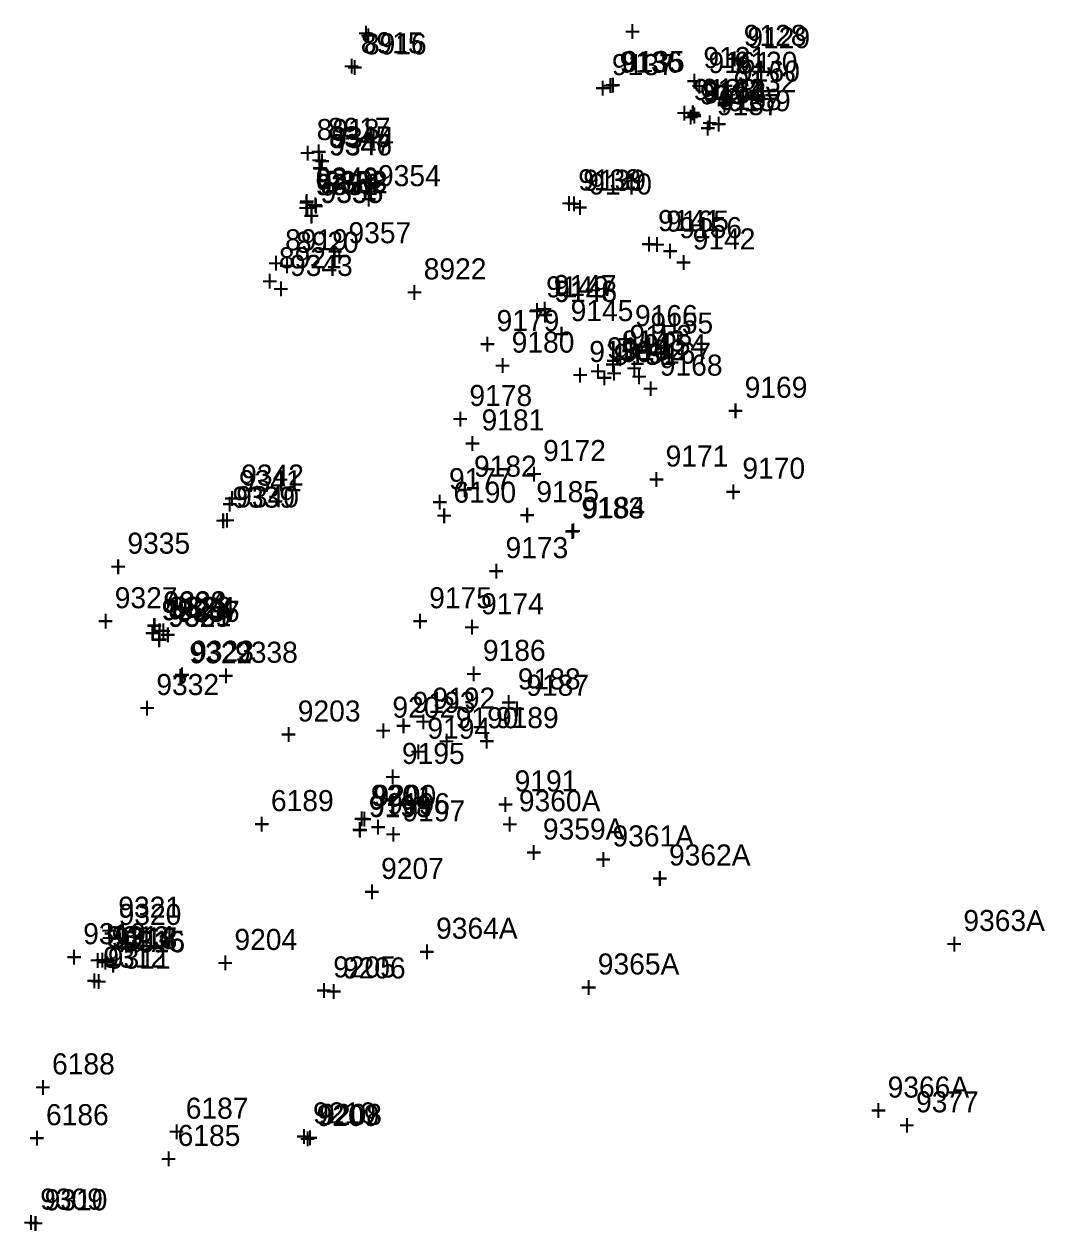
# Model space of a CAD drawing. Extents: x 1136220 to 1137808, y 528804 to 531215.
# Drawn here: x 1136326 to 1136447, y 529376.3 to 529519.5 of the extents above; entities that cross this region are included whole.
import ezdxf

# ---------------------------------------------------------------- set-up
doc = ezdxf.new("R2010")
doc.units = 0
for name, color, linetype in [('S_Buildings', 7, 'Continuous'), ('S_Buildings_SillElevation', 7, 'Continuous'), ('S_Curb_Type_3', 7, 'Continuous'), ('S_Drainage_CB', 7, 'Continuous'), ('S_Drainage_Culvert_Top', 7, 'Continuous'), ('S_Drainage_Invert', 7, 'Continuous'), ('S_Drainage_Sump', 7, 'Continuous'), ('S_Fencing_Picket', 7, 'Continuous'), ('S_Ground_Elevation', 7, 'Continuous'), ('S_Ground_LevelString', 7, 'Continuous'), ('S_Guardrail_Beam', 7, 'Continuous'), ('S_Property_Walkways', 7, 'Continuous'), ('S_Roadway_Centerline', 7, 'Continuous'), ('S_Roadway_Drive_Paved', 7, 'Continuous'), ('S_Roadway_Edge_Pavement', 7, 'Continuous'), ('S_Trees_Conifer_Pay', 7, 'Continuous'), ('S_Trees_Decid_Pay', 7, 'Continuous'), ('S_Trees_TreeLine', 7, 'Continuous'), ('S_Utilities_UG_Gas_Line', 7, 'Continuous'), ('S_Utilities_UG_Sanitary_MH', 7, 'Continuous')]:
    doc.layers.add(name, color=color, linetype=linetype)

msp = doc.modelspace()

# ---------------------------------------------------------------- texts
at = {"layer": 'S_Buildings'}
for s, p in [('9129', (1136411.76, 529516.64)), ('+', (1136409.7, 529513.89)), ('9142', (1136405.28, 529492.76)), ('+', (1136403.22, 529490.01))]:
    msp.add_text(s, height=2.5, dxfattribs=at).set_placement(p)
at = {"layer": 'S_Buildings_SillElevation'}
for s, p in [('9132', (1136410.13, 529511.42)), ('+', (1136408.07, 529508.67))]:
    msp.add_text(s, height=2.5, dxfattribs=at).set_placement(p)
at = {"layer": 'S_Curb_Type_3'}
for s, p in [('+', (1136365.56, 529517.2)), ('8915', (1136365.93, 529516.03)), ('+', (1136363.86, 529513.28)), ('9136', (1136396.62, 529513.74)), ('+', (1136394.56, 529510.99)), ('8918', (1136360.7, 529505.74)), ('+', (1136358.64, 529502.99)), ('9139', (1136392.3, 529499.72)), ('+', (1136390.24, 529496.97)), ('8919', (1136356.96, 529492.66)), ('8921', (1136356.22, 529490.53)), ('+', (1136354.9, 529489.91)), ('+', (1136354.16, 529487.78)), ('9147', (1136388.81, 529487.23)), ('9148', (1136388.87, 529486.55)), ('+', (1136386.75, 529484.48)), ('+', (1136386.81, 529483.8)), ('9341', (1136351.48, 529464.08)), ('9339', (1136350.7, 529462.13)), ('+', (1136349.42, 529461.33)), ('+', (1136348.64, 529459.38)), ('9322', (1136345.61, 529443.67)), ('+', (1136343.55, 529440.92)), ('9321', (1136337.18, 529413.49)), ('+', (1136335.12, 529410.74)), ('9313', (1136335.81, 529409.97)), ('+', (1136333.75, 529407.22)), ('9312', (1136335.41, 529407.55)), ('+', (1136333.35, 529404.8)), ('9209', (1136360.7, 529388.78)), ('+', (1136358.64, 529386.03)), ('9309', (1136327.92, 529378.86)), ('+', (1136325.86, 529376.11))]:
    msp.add_text(s, height=2.5, dxfattribs=at).set_placement(p)
at = {"layer": 'S_Drainage_CB'}
for s, p in [('9344', (1136362.43, 529504.78)), ('+', (1136360.37, 529502.03)), ('9350', (1136360.69, 529499.23)), ('+', (1136358.63, 529496.48)), ('9198', (1136366.92, 529425.41)), ('+', (1136364.86, 529422.66)), ('9315', (1136337.63, 529409.44)), ('+', (1136335.57, 529406.69))]:
    msp.add_text(s, height=2.5, dxfattribs=at).set_placement(p)
at = {"layer": 'S_Drainage_Culvert_Top'}
for s, p in [('9347', (1136362.15, 529503.95)), ('+', (1136360.09, 529501.2)), ('9348', (1136360.58, 529499.85)), ('9354', (1136367.97, 529500.27)), ('9356', (1136361.18, 529498.32)), ('9353', (1136361.62, 529499.58)), ('+', (1136365.9, 529497.52)), ('+', (1136358.52, 529497.1)), ('+', (1136359.56, 529496.83)), ('+', (1136359.12, 529495.57)), ('9357', (1136364.47, 529493.5)), ('+', (1136362.41, 529490.75)), ('9335', (1136338.26, 529456.67)), ('+', (1136336.19, 529453.92)), ('9327', (1136336.76, 529450.2)), ('9334', (1136342.51, 529449.66)), ('9326', (1136342.31, 529448.77)), ('9337', (1136344.15, 529448.58)), ('+', (1136334.7, 529447.45)), ('9331', (1136343.14, 529448.05)), ('+', (1136340.25, 529446.02)), ('+', (1136340.45, 529446.91)), ('+', (1136342.09, 529445.83)), ('+', (1136341.07, 529445.3)), ('9338', (1136351.03, 529443.73)), ('9332', (1136341.69, 529439.9)), ('+', (1136348.97, 529440.98)), ('+', (1136339.62, 529437.15)), ('9202', (1136369.68, 529437.21)), ('+', (1136367.62, 529434.46)), ('9201', (1136367.12, 529426.75)), ('+', (1136365.06, 529424)), ('9319', (1136333.02, 529410.34)), ('9318', (1136336.75, 529409.76)), ('+', (1136330.96, 529407.59)), ('+', (1136334.68, 529407.01))]:
    msp.add_text(s, height=2.5, dxfattribs=at).set_placement(p)
at = {"layer": 'S_Drainage_Invert'}
for s, p in [('9346', (1136362.2, 529503.91)), ('+', (1136360.14, 529501.16)), ('9349', (1136360.61, 529499.99)), ('9355', (1136361.15, 529498.27)), ('9352', (1136361.7, 529499.43)), ('+', (1136358.55, 529497.24)), ('+', (1136359.64, 529496.68)), ('+', (1136359.09, 529495.52)), ('9333', (1136342.56, 529449.71)), ('9325', (1136342.37, 529448.81)), ('9336', (1136344.13, 529448.58)), ('9329', (1136343.1, 529447.99)), ('+', (1136340.31, 529446.06)), ('+', (1136340.5, 529446.96)), ('+', (1136342.07, 529445.83)), ('+', (1136341.03, 529445.24)), ('9200', (1136367.43, 529426.73)), ('+', (1136365.37, 529423.98)), ('9317', (1136336.72, 529409.84)), ('+', (1136334.66, 529407.09))]:
    msp.add_text(s, height=2.5, dxfattribs=at).set_placement(p)
at = {"layer": 'S_Drainage_Sump'}
for s, p in [('9345', (1136362.09, 529504.88)), ('+', (1136360.03, 529502.13)), ('9351', (1136360.55, 529499.22)), ('+', (1136358.49, 529496.47)), ('9328', (1136343.15, 529449.07)), ('+', (1136341.09, 529446.32)), ('9199', (1136366.87, 529425.48)), ('+', (1136364.81, 529422.73)), ('9316', (1136337.67, 529409.38)), ('+', (1136335.61, 529406.63))]:
    msp.add_text(s, height=2.5, dxfattribs=at).set_placement(p)
at = {"layer": 'S_Fencing_Picket'}
for s, p in [('9362A', (1136402.47, 529419.68)), ('+', (1136400.41, 529416.93)), ('9363A', (1136437.37, 529411.91)), ('+', (1136435.31, 529409.16))]:
    msp.add_text(s, height=2.5, dxfattribs=at).set_placement(p)
at = {"layer": 'S_Ground_Elevation'}
for s, p in [('9128', (1136411.33, 529516.91)), ('9131', (1136406.55, 529514.28)), ('9135', (1136396.9, 529513.8)), ('+', (1136409.26, 529514.16)), ('9130', (1136410.26, 529513.72)), ('+', (1136404.49, 529511.53)), ('+', (1136394.84, 529511.05)), ('9133', (1136405.36, 529510.49)), ('9134', (1136406.13, 529509.98)), ('+', (1136408.2, 529510.97)), ('+', (1136403.3, 529507.74)), ('+', (1136404.07, 529507.23)), ('9140', (1136393.01, 529499.28)), ('+', (1136390.94, 529496.53)), ('9141', (1136401.17, 529494.94)), ('+', (1136399.11, 529492.19)), ('9146', (1136388.88, 529486.52)), ('9145', (1136390.81, 529484.26)), ('+', (1136386.82, 529483.77)), ('+', (1136388.75, 529481.51)), ('9144', (1136395.12, 529479.84)), ('9143', (1136396.9, 529480.66)), ('+', (1136394.84, 529477.91)), ('+', (1136393.06, 529477.09)), ('9188', (1136384.55, 529440.57)), ('+', (1136382.49, 529437.82)), ('9190', (1136377.19, 529435.96)), ('9189', (1136381.95, 529435.98)), ('9194', (1136373.83, 529434.72)), ('+', (1136375.13, 529433.21)), ('+', (1136379.89, 529433.23)), ('+', (1136371.77, 529431.97)), ('9197', (1136370.87, 529424.92)), ('9359A', (1136387.52, 529422.76)), ('+', (1136368.81, 529422.17)), ('+', (1136385.46, 529420.01)), ('9365A', (1136394.03, 529406.75)), ('+', (1136391.97, 529404)), ('9366A', (1136428.39, 529392.15)), ('+', (1136426.33, 529389.4))]:
    msp.add_text(s, height=2.5, dxfattribs=at).set_placement(p)
at = {"layer": 'S_Ground_LevelString'}
for s, p in [('9179', (1136382.03, 529483.08)), ('+', (1136379.97, 529480.33)), ('9180', (1136383.82, 529480.52)), ('+', (1136381.76, 529477.77)), ('9178', (1136378.81, 529474.19)), ('+', (1136376.75, 529471.44)), ('9181', (1136380.25, 529471.29)), ('+', (1136378.19, 529468.54)), ('9182', (1136379.35, 529465.8)), ('9177', (1136376.39, 529464.32)), ('+', (1136377.29, 529463.05)), ('+', (1136374.32, 529461.57))]:
    msp.add_text(s, height=2.5, dxfattribs=at).set_placement(p)
at = {"layer": 'S_Guardrail_Beam'}
for s, p in [('9192', (1136374.43, 529438.28)), ('+', (1136372.37, 529435.53)), ('9195', (1136370.81, 529431.73)), ('+', (1136368.75, 529428.98)), ('9196', (1136369.06, 529425.77)), ('+', (1136367, 529423.02)), ('9206', (1136363.81, 529406.28)), ('+', (1136361.75, 529403.53))]:
    msp.add_text(s, height=2.5, dxfattribs=at).set_placement(p)
at = {"layer": 'S_Property_Walkways'}
for s, p in [('9161', (1136407.15, 529513.69)), ('9160', (1136410.55, 529512.67)), ('+', (1136405.09, 529510.94)), ('9162', (1136406.38, 529510.51)), ('9163', (1136406.55, 529510.27)), ('9164', (1136406.55, 529510.1)), ('9157', (1136408.15, 529508.69)), ('9158', (1136408.39, 529509.31)), ('+', (1136408.49, 529509.92)), ('9159', (1136409.46, 529509.16)), ('+', (1136404.32, 529507.76)), ('+', (1136404.49, 529507.52)), ('+', (1136404.49, 529507.35)), ('+', (1136406.09, 529505.94)), ('+', (1136406.33, 529506.56)), ('+', (1136407.4, 529506.41)), ('9165', (1136402.14, 529494.88)), ('9156', (1136403.69, 529494.1)), ('+', (1136400.08, 529492.13)), ('+', (1136401.62, 529491.35)), ('9166', (1136398.44, 529483.67)), ('9155', (1136400.27, 529482.78)), ('+', (1136396.38, 529480.92)), ('+', (1136398.21, 529480.03))]:
    msp.add_text(s, height=2.5, dxfattribs=at).set_placement(p)
at = {"layer": 'S_Roadway_Centerline'}
for s, p in [('8922', (1136373.39, 529489.21)), ('+', (1136371.32, 529486.46)), ('9203', (1136358.46, 529436.76)), ('+', (1136356.4, 529434.01)), ('9204', (1136350.95, 529409.66)), ('+', (1136348.88, 529406.91))]:
    msp.add_text(s, height=2.5, dxfattribs=at).set_placement(p)
at = {"layer": 'S_Roadway_Drive_Paved'}
for s, p in [('9153', (1136397.79, 529481.32)), ('9152', (1136397.05, 529479.61)), ('9154', (1136399.43, 529480.2)), ('9150', (1136393.02, 529479.41)), ('+', (1136395.73, 529478.57)), ('9151', (1136395.9, 529479.07)), ('9167', (1136400.01, 529479.21)), ('+', (1136397.37, 529477.45)), ('9168', (1136401.38, 529477.79)), ('+', (1136390.96, 529476.66)), ('+', (1136393.83, 529476.32)), ('+', (1136394.99, 529476.86)), ('+', (1136397.95, 529476.46)), ('+', (1136399.32, 529475.04)), ('9169', (1136411.44, 529475.16)), ('+', (1136409.38, 529472.41)), ('9172', (1136387.55, 529467.66)), ('9171', (1136402.07, 529467.01)), ('9170', (1136411.17, 529465.56)), ('+', (1136385.49, 529464.91)), ('+', (1136400, 529464.26)), ('+', (1136409.11, 529462.81)), ('9173', (1136383.09, 529456.14)), ('+', (1136381.02, 529453.39)), ('9175', (1136374.04, 529450.2)), ('9174', (1136380.19, 529449.48)), ('+', (1136371.98, 529447.45)), ('+', (1136378.13, 529446.73))]:
    msp.add_text(s, height=2.5, dxfattribs=at).set_placement(p)
at = {"layer": 'S_Roadway_Edge_Pavement'}
for s, p in [('+', (1136365.85, 529516.91)), ('8916', (1136366.3, 529515.9)), ('+', (1136364.24, 529513.15)), ('9137', (1136395.7, 529513.44)), ('+', (1136393.64, 529510.69)), ('8917', (1136362.02, 529505.88)), ('+', (1136359.96, 529503.13)), ('9138', (1136391.71, 529499.77)), ('+', (1136389.65, 529497.02)), ('8920', (1136358.25, 529492.37)), ('9343', (1136357.54, 529489.62)), ('+', (1136356.19, 529489.62)), ('9149', (1136387.9, 529487.08)), ('+', (1136355.48, 529486.87)), ('+', (1136385.84, 529484.33)), ('9342', (1136351.75, 529464.75)), ('+', (1136349.68, 529462)), ('9340', (1136351.16, 529462.17)), ('+', (1136349.1, 529459.42)), ('9323', (1136345.82, 529443.85)), ('+', (1136343.76, 529441.1)), ('9193', (1136372.08, 529437.79)), ('+', (1136370.02, 529435.04)), ('9320', (1136337.22, 529412.63)), ('+', (1136335.16, 529409.88)), ('9314', (1136336.38, 529409.99)), ('+', (1136334.32, 529407.24)), ('9311', (1136335.94, 529407.45)), ('9205', (1136362.66, 529406.4)), ('+', (1136333.88, 529404.7)), ('+', (1136360.59, 529403.65)), ('9210', (1136360.27, 529389.08)), ('+', (1136358.21, 529386.33)), ('9310', (1136328.45, 529378.77)), ('+', (1136326.39, 529376.02))]:
    msp.add_text(s, height=2.5, dxfattribs=at).set_placement(p)
at = {"layer": 'S_Trees_Conifer_Pay'}
for s, p in [('9377', (1136431.76, 529390.4)), ('+', (1136429.7, 529387.65))]:
    msp.add_text(s, height=2.5, dxfattribs=at).set_placement(p)
at = {"layer": 'S_Trees_Decid_Pay'}
for s, p in [('9183', (1136392.08, 529460.85)), ('+', (1136390.02, 529458.1)), ('9191', (1136384.17, 529428.47)), ('+', (1136382.11, 529425.72)), ('9360A', (1136384.67, 529426.11)), ('+', (1136382.61, 529423.36)), ('9361A', (1136395.77, 529421.94)), ('+', (1136393.7, 529419.19))]:
    msp.add_text(s, height=2.5, dxfattribs=at).set_placement(p)
at = {"layer": 'S_Trees_TreeLine'}
for s, p in [('9185', (1136386.74, 529462.78)), ('+', (1136384.68, 529460.03)), ('9184', (1136392.21, 529460.91)), ('+', (1136390.15, 529458.16)), ('9186', (1136380.41, 529443.95)), ('+', (1136378.35, 529441.2)), ('9187', (1136385.55, 529439.81)), ('+', (1136383.49, 529437.06)), ('9207', (1136368.34, 529418.09)), ('+', (1136366.28, 529415.34)), ('9364A', (1136374.86, 529410.99)), ('+', (1136372.8, 529408.24)), ('9208', (1136361, 529388.91)), ('+', (1136358.94, 529386.16))]:
    msp.add_text(s, height=2.5, dxfattribs=at).set_placement(p)
at = {"layer": 'S_Utilities_UG_Gas_Line'}
for s, p in [('+', (1136397.16, 529517.4)), ('6189', (1136355.28, 529426.13)), ('+', (1136353.22, 529423.38)), ('6188', (1136329.33, 529394.9)), ('+', (1136327.27, 529392.15)), ('6187', (1136345.18, 529389.64)), ('6186', (1136328.61, 529388.87)), ('+', (1136326.55, 529386.12)), ('+', (1136343.12, 529386.89)), ('6185', (1136344.22, 529386.41)), ('+', (1136342.16, 529383.66))]:
    msp.add_text(s, height=2.5, dxfattribs=at).set_placement(p)
at = {"layer": 'S_Utilities_UG_Sanitary_MH'}
for s, p in [('6190', (1136376.91, 529462.72)), ('+', (1136374.84, 529459.97)), ('9324', (1136343.59, 529449.05)), ('+', (1136341.53, 529446.3))]:
    msp.add_text(s, height=2.5, dxfattribs=at).set_placement(p)

doc.saveas('drawing.dxf')
